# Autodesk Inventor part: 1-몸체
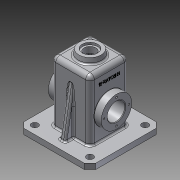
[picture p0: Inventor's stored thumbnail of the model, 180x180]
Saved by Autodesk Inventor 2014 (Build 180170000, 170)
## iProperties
Created: 2016-02
Part Number: 1-몸체
Material: 알루미늄 6061
Document SubType Name: Modeling
Designer: Administrator
Density: 2.71 g/cm^3
Appearance: 알루미늄 - 평지
Author: Administrator
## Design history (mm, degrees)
sketch "스케치1"
  geometry: L1 (65, -65)-(-65, -65); L2 (-65, -65)-(-65, 65); L3 (-65, 65)-(65, 65); L4 (65, 65)-(65, -65); L5 (65, -65)-(-65, 65); L6 (-65, -65)-(65, 65); 1 further point
  constraints: 12 end point, 2 midpoint, 2 parallel, 1 horizontal, 1 perpendicular
  dimensions: "d0" = 130 distance of L2.end L3.end; "d1" = 130 distance of L1.end L2.end
extrude "돌출1" new body sketch "스케치1" distance "d2" = 10; taper "d3" = 0 deg
sketch "스케치2"
  geometry: L1 (35, -35)-(-35, -35); L2 (-35, -35)-(-35, 35); L3 (-35, 35)-(35, 35); L4 (35, 35)-(35, -35); L5 (35, -35)-(-35, 35); L6 (-35, -35)-(35, 35); 1 further point
  constraints: 12 end point, 2 midpoint, 2 parallel, 1 horizontal, 1 perpendicular
  dimensions: "d4" = 70 distance of L1.end L2.end; "d5" = 70 distance of L2.end L3.end
extrude "돌출2" join sketch "스케치2" distance "d6" = 110; taper "d7" = 0 deg
feature "쉘1" dims "d9" = 10, "d10" = 5
fillet "모깎기3" dims "d54" = 8
fillet "모깎기4" dims "d55" = 8
fillet "모깎기5" dims "d56" = 3
fillet "모깎기6" dims "d57" = 3
node "작업 평면1"
sketch "스케치3"
  geometry: C1 r 20 at (0, 0); 1 further point
  constraints: 1 centre point, 1 coincident
  dimensions: "d12" = 40 diameter of C1
extrude "돌출3" join sketch "스케치3" stored distance "d13" = 110; taper "d14" = 10 deg
hole "구멍3" diameter "d46" = 21; stored, may be unused: countersink angle "d50" = 90 deg, drill point angle "d52" = 118 deg; dims "d44" = 10, "d45" = 10, "d47" = 32, "d48" = 28, "d49" = 4, "d51" = 10
sketch "스케치7"
  geometry: L1 (0, 27)-(55, 27); C1 r 27.5 at (55, 27)
  constraints: 2 end point, 1 centre point, 1 coincident, 1 horizontal
  dimensions: "d58" = 55 distance of L1.start L1.end; "d59" = 55 diameter of C1
extrude "돌출6" join sketch "스케치7" distance "d60" = 7; taper "d61" = 0 deg
sketch "스케치8"
  geometry: C1 r 27.5 at (-45, 27); A1 r 27.5 centre (-45, 27) between (-39.78, 0) and (-39.78, 54) reference; 1 further point
  constraints: 1 centre point, 1 coincident
  dimensions: "d62" = 55 diameter of C1
extrude "돌출7" join sketch "스케치8" distance "d63" = 13; taper "d64" = 0 deg
sketch "스케치9"
  geometry: L1 (0, 0)-(-22.5, 0); C1 r 27.5 at (0, 0) reference; 1 further point
  constraints: 2 end point, 1 horizontal
  dimensions: "d65" = 22.5 distance of L1.start L1.end
hole "구멍4" sketch "스케치9" at (-22.5, 0) diameter "d66" = 3.242; stored, may be unused: countersink angle "d70" = 90 deg, drill point angle "d72" = 118 deg; dims "d67" = 8, "d68" = 28, "d69" = 4, "d71" = 10
feature "면 기울기3" dims angle "d76" = 45 deg
feature "면 기울기4" dims angle "d77" = 45 deg
hole "구멍5" diameter "d80" = 32; stored, may be unused: countersink angle "d84" = 90 deg, drill point angle "d86" = 118 deg; dims "d78" = 10, "d79" = 10, "d81" = 8, "d82" = 28, "d83" = 4, "d85" = 10
sketch "스케치10"
  geometry: L1 (-65, 10)-(65, 10) reference; L2 (-35, 112)-(-35, 10) reference; L3 (-50, 10)-(-35, 95.069); L4 (-65, 0)-(-65, 10) reference; 1 further point
  constraints: 2 end point, 2 point on line
  dimensions: "d87" = 15 distance from line of L3.start L4; "d88" = 10 deg angle of L3 L4
feature "리브1" sketch "스케치10" dims "d89" = 1, "d90" = 10, "d91" = 0, "d92" = 0, "d93" = 1, "d94" = 1
sketch "스케치11"
  geometry: L1 (-50, -50)-(50, -50); L2 (50, -50)-(50, 50); L3 (50, 50)-(-50, 50); L4 (-50, 50)-(-50, -50); 3 further points
  constraints: 8 end point, 2 midpoint, 2 parallel, 1 horizontal, 1 horizontal alignment, 1 perpendicular, 1 vertical alignment
  dimensions: "d95" = 100 distance of L3.end L1.start; "d96" = 100 distance of L2.end L3.end
hole "구멍6" sketch "스케치11" at (-50, -50), (50, 50), (50, -50), (-50, 50) diameter "d97" = 12; stored, may be unused: countersink angle "d101" = 90 deg, drill point angle "d103" = 118 deg; dims "d98" = 8, "d99" = 28, "d100" = 4, "d102" = 10
chamfer "모따기1" distance "d104" = 10; stored, may be unused: second distance "d105" = 2, angle "d106" = 45 deg
fillet "모깎기7" dims "d107" = 0.5
fillet "모깎기8" dims "d108" = 0.5
fillet "모깎기9" dims "d109" = 0.5
chamfer "모따기2" distance "d110" = 1; stored, may be unused: second distance "d111" = 2, angle "d112" = 45 deg
fillet "모깎기10" dims "d113" = 3
fillet "모깎기11" dims "d114" = 3
fillet "모깎기12" dims "d115" = 3
fillet "모깎기13" dims "d116" = 3
sketch "스케치12"
  geometry: L1 (-18, 47)-(-18, 7) reference; L2 (99, 62)-(0, 62) reference; 2 further points
  constraints: 1 other
  dimensions: "d117" = 30 distance from line of point (12, 27) L1; "d118" = 35 distance from line of L2 point (12, 27)
feature "엠보싱1" sketch "스케치12" dims "d119" = 0.5, "d120" = 0
node "솔리드1"
pattern_circular "원형 패턴2" dims angle "d74" = 360 deg
mirror "대칭2"
mirror "대칭3"
